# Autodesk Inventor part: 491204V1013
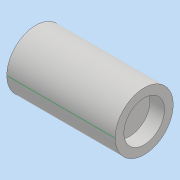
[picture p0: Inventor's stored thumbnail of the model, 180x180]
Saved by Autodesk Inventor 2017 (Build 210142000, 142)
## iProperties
Created: 2019-12
Part Number: 491204V1013
Material: Generic
Document SubType Name: Modeling
Designer: 5-09-le
Density: 1 g/cm^3
Appearance: Default
Author: 5-09-le
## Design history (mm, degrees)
sketch "스케치1"
  geometry: 1 further point
sketch "스케치2"
  geometry: C1 r 30 at (0, 0); 1 further point
  constraints: 1 centre point, 1 coincident
  dimensions: "d0" = 60 diameter of C1
extrude "돌출1" new body sketch "스케치2" stored distance "d1" = 112; taper "d2" = 0 deg
sketch "스케치3"
  geometry: L1 (-56, 30)-(-56, -30) reference; L2 (-56, -30)-(56, -30) reference; 1 further point
sketch "스케치4"
  geometry: C1 r 30 at (0, 0) reference; C2 r 21 at (0, 0)
  constraints: 1 centre point, 1 coincident
  dimensions: "d6" = 42 diameter of C2
extrude "돌출2" cut sketch "스케치4" distance "d7" = 15; taper "d8" = 0 deg
node "솔리드1"
